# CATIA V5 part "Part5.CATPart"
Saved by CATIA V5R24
Part number: Link4-2
Bounding box of the stored display mesh (mm): x -20 to 0, y 0 to 117.275, z -42.872 to 102.723
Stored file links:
  G:\_CAD수업\DMU_paradoxes\2\Part5.CATPart
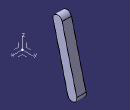
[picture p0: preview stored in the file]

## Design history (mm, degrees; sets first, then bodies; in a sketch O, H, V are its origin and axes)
AxisSystem1: origin (0, 0, 0), X (1, 0, 0), Y (0, 1, 0), Z (0, 0, 1)
Body1 (main body)
  Sketch1 on YZ plane of AxisSystem1, origin (0, 0, 0), H (0, 1, 0), V (0, 0, 1)
    line L1 (119.4029, -40.1493) -> (100, -45)
    line L2 (100, -45) -> (63.75, 100)
    line L3 (63.75, 100) -> (83.1529, 104.8507)
    line L4 (83.1529, 104.8507) -> (119.4029, -40.1493)
    length L3 = 20
    parallelism: L4 L2, L1 L3
    perpendicularity: L1 L2
  Pad1: profile Sketch1, direction (-1, 0, 0), length 20
  TritangentFillet1: Face1 face of Pad1 from Sketch1.L4, Face2 face of Pad1 from Sketch1.L2, RemoveFace face of Pad1 from Sketch1.L3
  TritangentFillet2: Face1 face of Pad1 from Sketch1.L2, Face2 face of Pad1 from Sketch1.L4, RemoveFace face of Pad1 from Sketch1.L1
